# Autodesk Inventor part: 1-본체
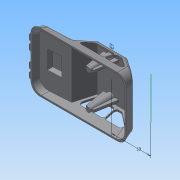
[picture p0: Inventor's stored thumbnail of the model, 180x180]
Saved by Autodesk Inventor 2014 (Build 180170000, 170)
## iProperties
Created: 2015-05
Part Number: 1-본체
Material: Generic
Document SubType Name: Modeling
Designer: Administrator
Density: 1 g/cm^3
Appearance: Default
Author: Administrator
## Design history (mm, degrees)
sketch "스케치1"
  geometry: L1 (0, 0)-(122, 0); L2 (54.451, 31)-(92, 31); L3 (92, 31)-(119.053, 11); L4 (119.053, 11)-(122, 0); L5 (0, 0)-(2.412, 9); L6 (2.412, 9)-(42, 11.075); L7 (42, 11.075)-(54.451, 31)
  constraints: 14 end point, 1 horizontal, 1 parallel
  dimensions: "d0" = 122 distance of L1.start L1.end; "d7" = 105 deg angle of L1 L4; "d8" = 31 distance between parallel lines of L1 L2; "d9" = 30 horizontal distance of L1.end L2.end; "d13" = 20 vertical distance of L3.end L2.end; "d16" = 105 deg angle of L5 L1; "d17" = 42 horizontal distance of L6.end L1.start; "d18" = 125 deg angle of L7 L6; "d19" = 9 distance from line of L5.end L1; "d22" = 3 deg angle of L1 L6
extrude "돌출1" new body sketch "스케치1" distance "d23" = 76; taper "d24" = 0 deg
sketch "스케치7"
  geometry: L1 (0, 0)-(0, 76) reference; L2 (31, 0)-(31, 76) reference; L3 (0, 76)-(31, 67.694); L4 (0, 0)-(31, 8.306); L5 (0, 76)-(11, 76) reference; L6 (11, 76)-(31, 76) reference; L7 (0, 0)-(11, 0) reference; L8 (11, 0)-(31, 0) reference
  constraints: 4 end point, 2 point on line
  dimensions: "d53" = 105 deg angle of L1 L4; "d54" = 105 deg angle of L3 L1
extrude "돌출5" cut sketch "스케치7" stored distance "d55" = 0; taper "d56" = 0 deg
sketch "스케치2"
  geometry: L1 (39.643, 76)-(0, 76) reference; L2 (0, 76)-(0, 0) reference; L3 (9.821, 51)-(29.821, 51); L4 (29.821, 51)-(29.821, 25); L5 (29.821, 25)-(9.821, 25); L6 (9.821, 25)-(9.821, 51); L7 (9.821, 51)-(29.821, 25); L8 (29.821, 51)-(9.821, 25); 6 further points
  constraints: 12 end point, 6 midpoint, 2 parallel, 1 horizontal, 1 horizontal alignment, 1 perpendicular, 1 vertical alignment
  dimensions: "d26" = 20 distance of L3.start L3.end; "d27" = 26 distance of L3.end L4.end
extrude "돌출2" join sketch "스케치2" distance "d28" = 5; taper "d29" = -20 deg
feature "쉘1" dims "d30" = 2
sketch "스케치3"
  geometry: L1 (119.053, 11)-(92, 31) reference; L2 (92, 31)-(54.451, 31) reference; L3 (54.451, 31)-(42, 11.075) reference; L4 (81.849, 26)-(57.222, 26); L5 (82.642, 26)-(82.642, 11); L6 (82.642, 11)-(110.642, 11); L7 (110.642, 11)-(90.352, 26); L8 (90.352, 26)-(82.642, 26); L9 (47.849, 11)-(57.222, 26); L10 (81.849, 26)-(81.849, 11); L11 (81.849, 11)-(47.849, 11)
  constraints: 16 end point, 4 perpendicular, 2 parallel
  dimensions: "d31" = 5 distance between parallel lines of L3 L9; "d32" = 5 distance between parallel lines of L4 L2; "d34" = 34 distance of L10.end L9.start; "d35" = 15 distance from line of L11 L4.end; "d36" = 5 distance between parallel lines of L2 L8; "d37" = 5 distance between parallel lines of L1 L7; "d38" = 28 distance of L5.end L6.end; "d39" = 15 distance between parallel lines of L6 L8
extrude "돌출3" cut sketch "스케치3" stored distance "d40" = 0; taper "d41" = 0 deg
node "작업 평면3"
sketch "스케치9"
  geometry: A1 r 4 centre (0, 59) between (0, 55) and (0, 63); A2 r 4 centre (0, 48) between (0, 44) and (0, 52); A3 r 4 centre (0, 28) between (0, 24) and (0, 32); A4 r 4 centre (0, 17) between (0, 13) and (0, 21); 3 further points
  constraints: 8 point on circle, 4 centre point, 3 equal radius, 14 other
  dimensions: "d58" = 8 diameter of A1; "d59" = 11 distance of A2.centre A1.centre; "d60" = 10 distance of A2.centre point (0, 38); "d61" = 11 distance of A4.centre A3.centre; "d62" = 10 distance of A3.centre point (0, 38)
extrude "돌출6" join sketch "스케치9" stored distance "d63" = 5; taper "d64" = 0 deg
sketch "스케치16"
  geometry: L1 (-54.451, 8.306)-(-54.451, 67.694) reference; L2 (-54.451, 67.694)-(-92, 67.694) reference; L3 (-92, 8.306)-(-92, 67.694) reference; L4 (-92, 8.306)-(-54.451, 8.306) reference; C1 r 3 at (-73.225, 60); C2 r 3 at (-73.225, 16); 4 further points
  constraints: 3 vertical alignment, 2 centre point, 2 midpoint, 1 horizontal alignment
  dimensions: "d85" = 6 diameter of C2; "d86" = 6 diameter of C1; "d87" = 22 distance of point (-73.225, 38) C2.centre; "d88" = 22 distance of C1.centre point (-73.225, 38)
extrude "돌출10" join sketch "스케치16" stored distance "d89" = 5; taper "d90" = 4 deg
node "작업 평면6"
sketch "스케치19"
  geometry: L1 (55.559, 29)-(91.341, 29) reference; L2 (63.689, 29)-(68.45, 2); L3 (68.45, 2)-(78.45, 2); L4 (78.45, 2)-(83.211, 29); L5 (0, 0)-(122, 0) reference; 2 further points
  constraints: 6 end point, 2 midpoint, 2 point on line, 1 equal length, 1 parallel, 1 vertical alignment
  dimensions: "d96" = 20 deg angle of L4 L2; "d97" = 10 distance of L2.end L3.end; "d98" = 2 distance between parallel lines of L5 L3
extrude "돌출12" join sketch "스케치19" stored distance "d99" = 3; taper "d100" = 0 deg
fillet "모깎기1" dims "d101" = 3
node "작업 평면7"
sketch "스케치20"
  geometry: L1 (55.559, 29)-(91.341, 29) reference; L2 (0, 0)-(122, 0) reference; L3 (63.689, 29)-(68.45, 2); L4 (68.45, 2)-(78.45, 2); L5 (78.45, 2)-(83.211, 29); 2 further points
  constraints: 6 end point, 2 midpoint, 2 point on line, 1 equal length, 1 parallel, 1 vertical alignment
  dimensions: "d103" = 2 distance between parallel lines of L2 L4; "d104" = 20 deg angle of L5 L3; "d105" = 10 distance of L3.end L4.end
extrude "돌출13" join sketch "스케치20" stored distance "d106" = 3; taper "d107" = 0 deg
fillet "모깎기2" dims "d108" = 3
fillet "모깎기3" dims "d109" = 3
fillet "모깎기5" dims "d111" = 12
fillet "모깎기6" dims "d112" = 3
fillet "모깎기7" dims "d113" = 3
chamfer "모따기1" distance "d114" = 1; stored, may be unused: second distance "d115" = 2, angle "d116" = 45 deg
sketch "스케치21"
  geometry: L1 (34.898, 0)-(0, 0) reference; L2 (34.898, 54.783)-(34.898, 0) reference; L3 (0, 54.783)-(34.898, 54.783) reference; L4 (0, 0)-(0, 54.783) reference; L5 (65.886, 53.8)-(65.886, 0.983) reference; 2 further points
  constraints: 1 other
  dimensions: "d117" = 50 distance from line of L5 point (15.886, 31.301)
node "솔리드1"
other parameters: "d57" = -2, "d95" = 16
